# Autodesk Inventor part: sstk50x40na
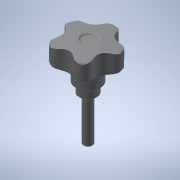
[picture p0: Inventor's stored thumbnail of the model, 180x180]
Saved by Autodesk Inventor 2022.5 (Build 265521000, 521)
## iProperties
Created: 2016-12
Part Number: sstk50x40na
Material: 一般
Document SubType Name: Modeling
Designer: imaocorp
Density: 1 g/cm^3
Appearance: 既定
Author: imaocorp
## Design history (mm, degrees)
node "sstk50x40na.x_t1"
node "sstk50x40na"
node "Base1"
